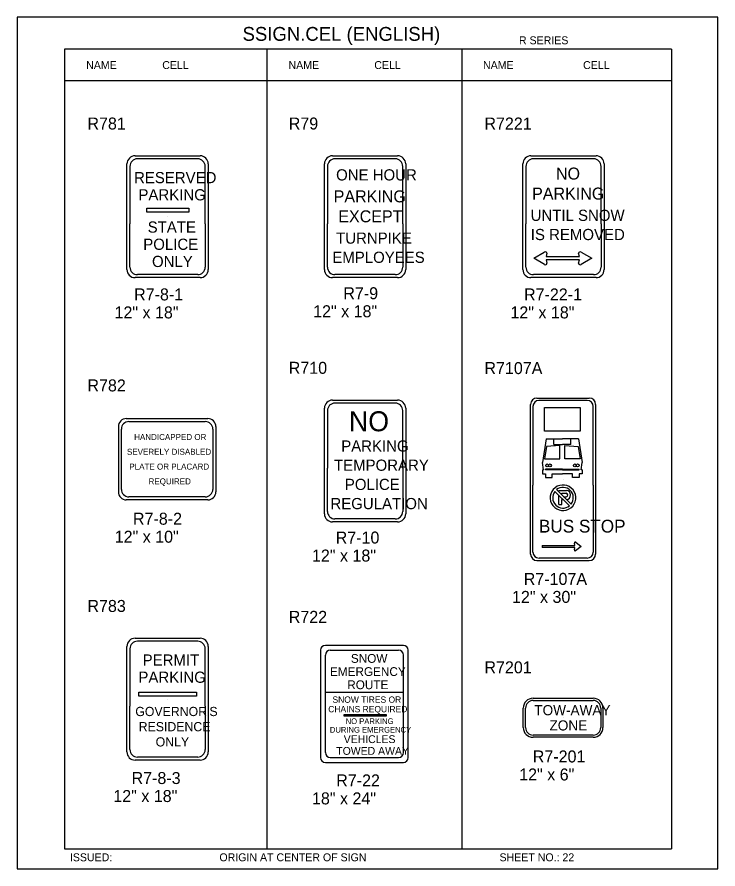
# Model space of a CAD drawing. Extents: x -5299 to 22597, y -19549 to -1808.
# Drawn here: x -2827 to -2126, y -6387 to -5535 of the extents above; entities that cross this region are included whole.
import ezdxf

# ---------------------------------------------------------------- set-up
doc = ezdxf.new("R2010")
doc.units = 0
for name, color, linetype in [('Level 1', 7, 'Continuous'), ('Level 2', 7, 'Continuous'), ('Level 3', 7, 'Continuous'), ('Level 63', 7, 'Continuous')]:
    doc.layers.add(name, color=color, linetype=linetype)

msp = doc.modelspace()

# ---------------------------------------------------------------- linework, layer by layer
at = {"layer": 'Level 1'}
for p, q in [((-2172.62, -5567.18), (-2779.63, -5567.18)), ((-2779.63, -5567.18), (-2779.63, -6367.18)), ((-2577.29, -5567.18), (-2577.29, -6367.18)), ((-2382.16, -5567.18), (-2382.16, -6367.18)), ((-2172.62, -5567.18), (-2172.62, -6367.18)), ((-2172.62, -5598.85), (-2779.63, -5598.85)), ((-2714.19, -5684.37), (-2714.19, -5741.94)), ((-2646.47, -5676.86), (-2706.67, -5676.86)), ((-2638.95, -5741.94), (-2638.95, -5684.37)), ((-2516.67, -5684.37), (-2516.67, -5741.94)), ((-2448.95, -5676.86), (-2509.15, -5676.86)), ((-2441.43, -5741.94), (-2441.43, -5684.37)), ((-2318.2, -5684.37), (-2318.2, -5741.94)), ((-2250.47, -5676.86), (-2310.68, -5676.86)), ((-2242.96, -5741.94), (-2242.96, -5684.37)), ((-2676.57, -5734.8), (-2676.57, -5734.8)), ((-2479.05, -5734.8), (-2479.05, -5734.8)), ((-2280.58, -5734.8), (-2280.58, -5734.8)), ((-2714.19, -5785.22), (-2714.19, -5741.94)), ((-2638.95, -5741.94), (-2638.95, -5785.22)), ((-2516.67, -5785.22), (-2516.67, -5741.94)), ((-2441.43, -5741.94), (-2441.43, -5785.22)), ((-2318.2, -5785.22), (-2318.2, -5741.94)), ((-2242.96, -5741.94), (-2242.96, -5785.22)), ((-2310.4, -5776.32), (-2299.81, -5770.19)), ((-2262.85, -5770.19), (-2252.26, -5776.32)), ((-2299.71, -5782.51), (-2310.4, -5776.32)), ((-2297.21, -5771.25), (-2298.03, -5774.67)), ((-2298.03, -5774.67), (-2281.33, -5774.67)), ((-2281.33, -5777.94), (-2297.98, -5777.94)), ((-2297.98, -5777.94), (-2297.14, -5781.41)), ((-2281.33, -5774.67), (-2281.33, -5774.67)), ((-2281.33, -5774.67), (-2264.63, -5774.67)), ((-2264.68, -5777.94), (-2281.33, -5777.94)), ((-2265.52, -5781.41), (-2264.68, -5777.94)), ((-2264.63, -5774.67), (-2265.45, -5771.25)), ((-2252.26, -5776.32), (-2262.95, -5782.51)), ((-2646.47, -5792.74), (-2706.67, -5792.74)), ((-2448.95, -5792.74), (-2509.15, -5792.74)), ((-2250.48, -5792.74), (-2310.68, -5792.74)), ((-2448.95, -5921.29), (-2509.15, -5921.29)), ((-2256.92, -5918.64), (-2305.09, -5918.64)), ((-2516.67, -5928.81), (-2516.67, -5986.37)), ((-2441.43, -5986.37), (-2441.43, -5928.81)), ((-2311.1, -5924.65), (-2311.1, -6003.21)), ((-2250.91, -6003.21), (-2250.91, -5924.65)), ((-2715.29, -5939.82), (-2638.83, -5939.82)), ((-2722.81, -6007.54), (-2722.81, -5947.34)), ((-2631.31, -5947.34), (-2631.31, -6007.54)), ((-2297.9, -5957.05), (-2301.42, -5980.54)), ((-2297.9, -5957.05), (-2281.69, -5957.05)), ((-2290.28, -5962.77), (-2290.28, -5957.05)), ((-2265.48, -5957.05), (-2281.69, -5957.05)), ((-2273.11, -5962.77), (-2273.11, -5957.05)), ((-2265.48, -5957.05), (-2261.96, -5980.54)), ((-2297.62, -5964.8), (-2299.45, -5976.98)), ((-2290.28, -5962.77), (-2281.69, -5962.77)), ((-2273.11, -5962.77), (-2281.69, -5962.77)), ((-2265.77, -5964.8), (-2263.94, -5976.98)), ((-2678.88, -5977.44), (-2678.88, -5977.44)), ((-2479.05, -5979.23), (-2479.05, -5979.23)), ((-2301.42, -5980.54), (-2301.42, -5980.54)), ((-2300.47, -5988.17), (-2301.42, -5980.54)), ((-2262.91, -5988.17), (-2261.96, -5980.54)), ((-2261.96, -5980.54), (-2261.96, -5980.54)), ((-2516.67, -6029.65), (-2516.67, -5986.37)), ((-2441.43, -5986.37), (-2441.43, -6029.65)), ((-2301.42, -5988.17), (-2301.42, -5988.17)), ((-2301.42, -5988.17), (-2300.47, -5988.17)), ((-2281.69, -5987.21), (-2298.56, -5987.21)), ((-2298.56, -5988.17), (-2298.56, -5987.21)), ((-2281.69, -5988.17), (-2298.56, -5988.17)), ((-2281.69, -5987.21), (-2264.82, -5987.21)), ((-2281.69, -5988.17), (-2264.82, -5988.17)), ((-2264.82, -5988.17), (-2264.82, -5987.21)), ((-2261.96, -5988.17), (-2262.91, -5988.17)), ((-2261.96, -5988.17), (-2261.96, -5988.17)), ((-2281.01, -5997.5), (-2281.01, -5997.5)), ((-2311.1, -6070.35), (-2311.1, -6003.21)), ((-2287.48, -6007.86), (-2272.95, -6022.39)), ((-2250.91, -6003.21), (-2250.91, -6070.35)), ((-2638.83, -6015.06), (-2715.29, -6015.06)), ((-2289.21, -6009.56), (-2274.66, -6024.11)), ((-2282.39, -6017.69), (-2281.1, -6017.69)), ((-2280.45, -6014.89), (-2277.83, -6014.89)), ((-2448.95, -6037.17), (-2509.15, -6037.17)), ((-2301.95, -6063.6), (-2277.59, -6063.6)), ((-2301.95, -6063.6), (-2301.95, -6065.82)), ((-2277.59, -6065.82), (-2301.95, -6065.82)), ((-2277.59, -6063.6), (-2269.25, -6063.6)), ((-2269.28, -6065.82), (-2277.59, -6065.82)), ((-2269.69, -6068.18), (-2269.28, -6065.82)), ((-2269.25, -6063.6), (-2269.66, -6061.27)), ((-2263.07, -6064.72), (-2268.41, -6068.93)), ((-2268.36, -6060.55), (-2263.07, -6064.72)), ((-2256.92, -6076.37), (-2305.08, -6076.37)), ((-2646.47, -6159.54), (-2706.67, -6159.54)), ((-2714.19, -6167.06), (-2714.19, -6224.62)), ((-2638.95, -6224.62), (-2638.95, -6167.06)), ((-2676.57, -6217.48), (-2676.57, -6217.48)), ((-2479.73, -6222.19), (-2479.73, -6222.19)), ((-2714.19, -6267.9), (-2714.19, -6224.62)), ((-2638.95, -6224.62), (-2638.95, -6267.9)), ((-2280.94, -6236.12), (-2280.94, -6236.12)), ((-2646.47, -6275.42), (-2706.67, -6275.42)), ((-2779.63, -6367.18), (-2172.62, -6367.18))]:
    msp.add_line(p, q, dxfattribs=at)
for points in [[(-2697.38, -5730.37), (-2697.38, -5726.17), (-2655.47, -5726.17), (-2655.47, -5730.37)], [(-2299.72, -5925.81), (-2263.88, -5925.81), (-2263.88, -5949.23), (-2299.72, -5949.23)], [(-2705.36, -6214.62), (-2705.36, -6210.43), (-2647.56, -6210.43), (-2647.56, -6214.62)]]:
    msp.add_lwpolyline(points, close=True, dxfattribs=at)
for points in [[(-2299.45, -5976.98), (-2284.19, -5976.98), (-2284.19, -5963.63), (-2297.62, -5964.8)], [(-2263.94, -5976.98), (-2279.2, -5976.98), (-2279.2, -5963.63), (-2265.77, -5964.8)], [(-2301.42, -5988.17), (-2301.42, -5991.98), (-2298.56, -5991.98), (-2298.56, -5995.8), (-2291.89, -5995.8), (-2291.89, -5991.98), (-2281.69, -5991.98)], [(-2261.96, -5988.17), (-2261.96, -5991.98), (-2264.82, -5991.98), (-2264.82, -5995.8), (-2271.5, -5995.8), (-2271.5, -5991.98), (-2281.69, -5991.98)], [(-2285.18, -6010.16), (-2285.18, -6008.57), (-2277.59, -6008.61)], [(-2285.2, -6022.84), (-2285.18, -6013.61)], [(-2285.2, -6022.84), (-2285.2, -6022.86), (-2282.39, -6022.84), (-2282.39, -6017.69)], [(-2282.39, -6012.95), (-2282.39, -6011.39), (-2277.91, -6011.4)]]:
    msp.add_lwpolyline(points, dxfattribs=at)
for centre in [(-2296.97, -5983.61), (-2294.11, -5983.61), (-2269.27, -5983.61), (-2266.41, -5983.61)]:
    msp.add_circle(centre, 1.43, dxfattribs=at)
for centre, radius, start, end in [((-2706.67, -5684.37), 7.52, 90, 180), ((-2646.47, -5684.37), 7.52, 0, 90), ((-2509.15, -5684.37), 7.52, 90, 180), ((-2448.95, -5684.37), 7.52, 0, 90), ((-2310.68, -5684.37), 7.52, 90, 180), ((-2250.47, -5684.37), 7.52, 0, 90), ((-2706.67, -5785.22), 7.52, 180, 270), ((-2646.47, -5785.22), 7.52, 270, 0), ((-2509.15, -5785.22), 7.52, 180, 270), ((-2448.95, -5785.22), 7.52, 270, 0), ((-2310.68, -5785.22), 7.52, 180, 270), ((-2250.48, -5785.22), 7.52, 270, 0), ((-2509.15, -5928.81), 7.52, 90, 180), ((-2448.95, -5928.81), 7.52, 0, 90), ((-2305.09, -5924.65), 6.02, 90, 180), ((-2256.92, -5924.65), 6.02, 0, 90), ((-2715.29, -5947.34), 7.52, 90, 180), ((-2638.83, -5947.34), 7.52, 0, 90), ((-2715.29, -6007.54), 7.52, 180, 270), ((-2638.83, -6007.54), 7.52, 270, 0), ((-2281.08, -6015.98), 12.79, 308.11415, 307.76212), ((-2281.07, -6015.97), 10.34, 321.95826, 128.34318), ((-2278.05, -6013.15), 4.56, 274.98032, 84.26909), ((-2281.07, -6015.97), 10.34, 142.1255, 308.3331), ((-2278.07, -6013.16), 1.76, 278.04391, 85.86111), ((-2509.15, -6029.65), 7.52, 180, 270), ((-2448.95, -6029.65), 7.52, 270, 0), ((-2268.87, -6061.17), 0.789, 49.85914, 190.52466), ((-2268.91, -6068.32), 0.789, 168.24762, 312.15425), ((-2305.08, -6070.35), 6.02, 180, 270), ((-2256.92, -6070.35), 6.02, 270, 0), ((-2706.67, -6167.06), 7.52, 90, 180), ((-2646.47, -6167.06), 7.52, 0, 90), ((-2706.67, -6267.9), 7.52, 180, 270), ((-2646.47, -6267.9), 7.52, 270, 0)]:
    msp.add_arc(centre, radius, start, end, dxfattribs=at)
for centre, start_param, end_param in [((-2298.8, -5771.11), 2.957903, 5.412979), ((-2263.87, -5771.11), 4.011799, 6.466875), ((-2298.71, -5781.61), 0.835066, 3.34671), ((-2263.95, -5781.61), 6.078068, 8.589712)]:
    msp.add_ellipse(centre, major_axis=(-1.58, 0), ratio=0.7337, start_param=start_param, end_param=end_param, dxfattribs=at)
at = {"layer": 'Level 2'}
for p, q in [((-2513.89, -6168.51), (-2445.57, -6168.51)), ((-2518.77, -6270.99), (-2518.77, -6173.39)), ((-2440.69, -6270.99), (-2440.69, -6173.39)), ((-2513.89, -6275.87), (-2445.57, -6275.87))]:
    msp.add_line(p, q, dxfattribs=at)
for centre, start, end in [((-2513.89, -6173.39), 90, 180), ((-2445.57, -6173.39), 0, 90), ((-2513.89, -6270.99), 180, 270), ((-2445.57, -6270.99), 270, 0)]:
    msp.add_arc(centre, 4.88, start, end, dxfattribs=at)
at = {"layer": 'Level 3'}
for p, q in [((-2709.08, -5673.84), (-2644.06, -5673.84)), ((-2511.56, -5673.84), (-2446.54, -5673.84)), ((-2313.09, -5673.84), (-2248.07, -5673.84)), ((-2717.21, -5741.94), (-2717.21, -5681.97)), ((-2635.93, -5681.97), (-2635.93, -5741.94)), ((-2519.69, -5741.94), (-2519.69, -5681.97)), ((-2438.41, -5681.97), (-2438.41, -5741.94)), ((-2321.21, -5741.94), (-2321.21, -5681.97)), ((-2239.94, -5681.97), (-2239.94, -5741.94)), ((-2717.21, -5787.63), (-2717.21, -5741.94)), ((-2635.93, -5741.94), (-2635.93, -5787.63)), ((-2519.69, -5787.63), (-2519.69, -5741.94)), ((-2438.41, -5741.94), (-2438.41, -5787.63)), ((-2321.21, -5787.63), (-2321.21, -5741.94)), ((-2239.94, -5741.94), (-2239.94, -5787.63)), ((-2644.05, -5795.75), (-2709.09, -5795.75)), ((-2446.53, -5795.75), (-2511.57, -5795.75)), ((-2248.06, -5795.75), (-2313.09, -5795.75)), ((-2511.56, -5918.27), (-2446.54, -5918.27)), ((-2313.52, -6003.21), (-2313.52, -5922.62)), ((-2307.12, -5916.22), (-2254.89, -5916.22)), ((-2248.49, -5922.62), (-2248.49, -6003.21)), ((-2519.69, -5986.37), (-2519.69, -5926.4)), ((-2438.41, -5926.4), (-2438.41, -5986.37)), ((-2717.83, -5936.8), (-2636.29, -5936.8)), ((-2725.83, -5944.8), (-2725.83, -6010.08)), ((-2628.29, -5944.8), (-2628.29, -6010.08)), ((-2519.69, -6032.07), (-2519.69, -5986.37)), ((-2438.41, -5986.37), (-2438.41, -6032.07)), ((-2313.51, -6072.38), (-2313.51, -6003.21)), ((-2248.49, -6003.21), (-2248.49, -6072.38)), ((-2636.29, -6018.08), (-2717.83, -6018.08)), ((-2446.53, -6040.19), (-2511.57, -6040.19)), ((-2307.11, -6078.78), (-2254.89, -6078.78)), ((-2709.08, -6156.52), (-2644.06, -6156.52)), ((-2717.21, -6224.62), (-2717.21, -6164.65)), ((-2635.93, -6164.65), (-2635.93, -6224.62)), ((-2523.65, -6168.51), (-2523.65, -6275.87)), ((-2440.69, -6163.63), (-2518.77, -6163.63)), ((-2435.81, -6275.87), (-2435.81, -6168.51)), ((-2518.62, -6210.4), (-2440.48, -6210.4)), ((-2311.05, -6216.58), (-2250.84, -6216.58)), ((-2311.05, -6218.82), (-2250.84, -6218.82)), ((-2717.21, -6270.32), (-2717.21, -6224.62)), ((-2635.93, -6224.62), (-2635.93, -6270.32)), ((-2320.8, -6245.9), (-2320.8, -6226.34)), ((-2318.57, -6245.9), (-2318.57, -6226.34)), ((-2243.32, -6226.34), (-2243.32, -6245.9)), ((-2241.09, -6226.34), (-2241.09, -6245.9)), ((-2250.84, -6253.42), (-2311.05, -6253.42)), ((-2250.84, -6255.66), (-2311.05, -6255.66)), ((-2644.05, -6278.44), (-2709.09, -6278.44)), ((-2518.77, -6280.75), (-2440.69, -6280.75))]:
    msp.add_line(p, q, dxfattribs=at)
msp.add_lwpolyline([(-2500.12, -6232.89), (-2457.94, -6232.89), (-2457.94, -6234.41), (-2500.12, -6234.41)], close=True, dxfattribs=at)
for centre, radius, start, end in [((-2709.08, -5681.97), 8.13, 90, 180), ((-2644.06, -5681.97), 8.13, 0, 90), ((-2511.56, -5681.97), 8.13, 90, 180), ((-2446.54, -5681.97), 8.13, 0, 90), ((-2313.09, -5681.97), 8.13, 90, 180), ((-2248.07, -5681.97), 8.13, 0, 90), ((-2709.09, -5787.63), 8.12, 180, 270), ((-2644.05, -5787.63), 8.12, 270, 0), ((-2511.57, -5787.63), 8.12, 180, 270), ((-2446.53, -5787.63), 8.12, 270, 0), ((-2313.09, -5787.63), 8.12, 180, 270), ((-2248.06, -5787.63), 8.12, 270, 0), ((-2511.56, -5926.4), 8.13, 90, 180), ((-2446.54, -5926.4), 8.13, 0, 90), ((-2307.12, -5922.62), 6.4, 90, 180), ((-2254.89, -5922.62), 6.4, 0, 90), ((-2717.83, -5944.8), 8, 90, 180), ((-2636.29, -5944.8), 8, 0, 90), ((-2717.83, -6010.08), 8, 180, 270), ((-2636.29, -6010.08), 8, 270, 0), ((-2511.57, -6032.07), 8.12, 180, 270), ((-2446.53, -6032.07), 8.12, 270, 0), ((-2307.11, -6072.38), 6.4, 180, 270), ((-2254.89, -6072.38), 6.4, 270, 0), ((-2709.08, -6164.65), 8.13, 90, 180), ((-2644.06, -6164.65), 8.13, 0, 90), ((-2518.77, -6168.51), 4.88, 90, 180), ((-2440.69, -6168.51), 4.88, 0, 90), ((-2311.05, -6226.34), 9.75, 90, 180), ((-2311.05, -6226.34), 7.52, 90, 180), ((-2250.84, -6226.34), 9.75, 0, 90), ((-2250.84, -6226.34), 7.52, 0, 90), ((-2311.05, -6245.9), 9.75, 180, 270), ((-2311.05, -6245.9), 7.52, 180, 270), ((-2250.84, -6245.9), 7.52, 270, 0), ((-2250.84, -6245.9), 9.75, 270, 0), ((-2709.09, -6270.32), 8.12, 180, 270), ((-2644.05, -6270.32), 8.12, 270, 0), ((-2518.77, -6275.87), 4.88, 180, 270), ((-2440.69, -6275.87), 4.88, 270, 0)]:
    msp.add_arc(centre, radius, start, end, dxfattribs=at)
at = {"layer": 'Level 63'}
msp.add_lwpolyline([(-2827.14, -6387.37), (-2126.09, -6387.37), (-2126.09, -5534.99), (-2827.14, -5534.99)], close=True, dxfattribs=at)

# ---------------------------------------------------------------- texts
at = {"layer": 'Level 1'}
for s, height, p in [('RESERVED', 11.2, (-2710.12, -5701.23)), ('ONE HOUR', 11.2, (-2508.03, -5698.51)), ('NO', 12, (-2288.13, -5697.62)), ('PARKING', 11.2, (-2705.72, -5718.43)), ('PARKING', 12, (-2510.45, -5720.4)), ('PARKING', 12, (-2311.98, -5717.62)), ('UNTIL SNOW', 11.2, (-2313.47, -5738.99)), ('EXCEPT', 12, (-2505.84, -5740.4)), ('STATE', 11.2, (-2696.49, -5750.73)), ('TURNPIKE', 11.2, (-2507.99, -5761.77)), ('IS REMOVED', 11.2, (-2313.3, -5758.19)), ('POLICE', 11.2, (-2700.89, -5767.93)), ('EMPLOYEES', 11.2, (-2511.8, -5780.97)), ('ONLY', 11.2, (-2692.15, -5785.13)), ('NO', 20, (-2495.2, -5949.44)), ('HANDICAPPED OR', 6, (-2710.01, -5958.18)), ('PARKING', 11.2, (-2502.9, -5969.79)), ('SEVERELY DISABLED', 6, (-2717.21, -5972.98)), ('PLATE OR PLACARD', 6, (-2714.81, -5987.78)), ('TEMPORARY', 11.2, (-2510.13, -5988.99)), ('REQUIRED', 6, (-2695.61, -6002.58)), ('POLICE', 11.2, (-2499.27, -6008.19)), ('REGULATION', 11.2, (-2513.7, -6027.39)), ('BUS STOP', 12.8, (-2305.09, -6050.77)), ('PERMIT', 11.2, (-2701.49, -6183.91)), ('PARKING', 11.2, (-2705.72, -6201.11)), ("GOVERNOR'S", 9.2, (-2708.87, -6234.41)), ('TOW-AWAY', 10.159, (-2309.77, -6233.58)), ('ZONE', 10.159, (-2294.59, -6248.82)), ('RESIDENCE', 9.2, (-2705.47, -6249.61)), ('ONLY', 9.2, (-2688.52, -6264.81))]:
    msp.add_text(s, height=height, dxfattribs=at).set_placement(p)
at = {"layer": 'Level 2'}
for s, height, p in [('R781', 12, (-2756.74, -5647.53)), ('R79', 12, (-2555.37, -5647.53)), ('R7221', 12, (-2359.67, -5647.53)), ('R7-8-1', 12, (-2710.05, -5818.54)), ('R7-9', 12, (-2500.78, -5817.36)), ('R7-22-1', 12, (-2320.06, -5818.54)), ('12" x 18"', 12, (-2729.66, -5836.54)), ('12" x 18"', 12, (-2530.97, -5835.36)), ('12" x 18"', 12, (-2333.67, -5836.54)), ('R710', 12, (-2555.37, -5891.97)), ('R7107A', 12, (-2359.67, -5892.21)), ('R782', 12, (-2756.74, -5909.57)), ('R7-8-2', 12, (-2711.2, -6042.94)), ('12" x 10"', 12, (-2729.44, -6060.94)), ('R7-10', 12, (-2508.43, -6061.8)), ('12" x 18"', 12, (-2532.14, -6079.8)), ('R7-107A', 12, (-2320.35, -6103.17)), ('12" x 30"', 12, (-2332.07, -6121.17)), ('R783', 12, (-2756.74, -6130.22)), ('R722', 12, (-2555.37, -6141.13)), ('SNOW', 8.784, (-2493.22, -6181.12)), ('R7201', 12, (-2359.67, -6191.64)), ('EMERGENCY', 8.784, (-2514.13, -6194.3)), ('ROUTE', 8.784, (-2496.86, -6207.47)), ('SNOW TIRES OR', 6.3407, (-2511.64, -6221.1)), ('CHAINS REQUIRED', 6.3395, (-2515.88, -6230.61)), ('NO PARKING', 5.707, (-2498.49, -6242.39)), ('DURING EMERGENCY', 5.7056, (-2514.29, -6250.95)), ('VEHICLES', 7.827, (-2500.41, -6261.41)), ('TOWED AWAY', 7.827, (-2507.87, -6273.15)), ('R7-201', 12, (-2311.29, -6280.82)), ('R7-8-3', 12, (-2712.6, -6302.4)), ('12" x 6"', 12, (-2324.89, -6298.82)), ('R7-22', 12, (-2507.91, -6304.77)), ('12" x 18"', 12, (-2730.84, -6320.4)), ('18" x 24"', 12, (-2532.14, -6322.77))]:
    msp.add_text(s, height=height, dxfattribs=at).set_placement(p)
at = {"layer": 'Level 3'}
for s, height, p in [('SSIGN.CEL (ENGLISH)', 13.8566, (-2601.56, -5558.79)), ('R SERIES', 7.918, (-2325.12, -5562.23)), ('NAME', 7.918, (-2758.03, -5587.01)), ('CELL', 7.918, (-2681.9, -5587.01)), ('NAME', 7.918, (-2555.62, -5587.01)), ('CELL', 7.918, (-2469.83, -5587.01)), ('NAME', 7.918, (-2361.06, -5587.01)), ('CELL', 7.918, (-2261, -5587.01)), ('ISSUED:', 7.918, (-2774.27, -6379.67)), ('ORIGIN AT CENTER OF SIGN', 7.9181, (-2624.73, -6379.67)), ('SHEET NO.: 22', 7.918, (-2344.58, -6379.67))]:
    msp.add_text(s, height=height, dxfattribs=at).set_placement(p)

doc.saveas('drawing.dxf')
